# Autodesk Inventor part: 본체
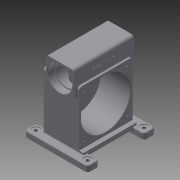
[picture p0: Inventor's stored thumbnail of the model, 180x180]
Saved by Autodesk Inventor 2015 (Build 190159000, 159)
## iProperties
Created: 2025-06
Part Number: 본체
Material: 일반
Document SubType Name: Modeling
Designer: User
Density: 1 g/cm^3
Appearance: 기본값
Author: User
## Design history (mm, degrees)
sketch "스케치1"
  geometry: L1 (-93, -103)-(93, -103); L2 (93, -103)-(93, 103); L3 (93, 103)-(-93, 103); L4 (-93, 103)-(-93, -103); L5 (-93, -103)-(93, 103); L6 (93, -103)-(-93, 103); 1 further point
  constraints: 12 end point, 2 midpoint, 2 parallel, 1 horizontal, 1 perpendicular
  dimensions: "d0" = 186 distance of L3.end L2.end; "d1" = 206 distance of L2.end L1.end
extrude "돌출1" new body sketch "스케치1" distance "d2" = 125; taper "d3" = 0 deg
sketch "스케치2"
  geometry: L1 (103, -93)-(103, 93) reference; L2 (103, 93)-(-103, 93) reference; L3 (103, -93)-(86, -93); L4 (86, -93)-(86, 93); L5 (86, 93)-(103, 93); L6 (103, 93)-(103, -93); 1 further point
  constraints: 8 end point, 2 parallel, 1 horizontal, 1 perpendicular, 1 point on line
  dimensions: "d4" = 17 distance between parallel lines of L1 L4
extrude "돌출2" join sketch "스케치2" distance "d5" = 15; taper "d6" = 0 deg
node "작업 평면1"
sketch "스케치3"
  geometry: L1 (-22, 158)-(-118, 158); L2 (-118, 158)-(-118, 62); L3 (-118, 62)-(-22, 62); L4 (-22, 62)-(-22, 158); L5 (-22, 158)-(-118, 62); L6 (-118, 158)-(-22, 62); L7 (0, -103)-(0, 103) reference; L8 (0, -103)-(-140, -103) reference; 2 further points
  constraints: 12 end point, 2 midpoint, 2 parallel, 1 horizontal, 1 perpendicular
  dimensions: "d8" = 96 distance of L3.end L2.end; "d9" = 96 distance of L2.end L1.end; "d10" = 70 distance from line of L7 point (-70, 110); "d11" = 261 distance between parallel lines of L8 L1
extrude "돌출3" join sketch "스케치3" stored distance "d12" = 210; taper "d13" = 0 deg
fillet "모깎기1" dims "d14" = 10
sketch "스케치4"
  geometry: A1 r 10 centre (108, -72) between (118, -72) and (108, -62) reference; A2 r 10 centre (32, -72) between (32, -62) and (22, -72) reference; A3 r 10 centre (32, -148) between (22, -148) and (32, -158) reference; A4 r 10 centre (108, -148) between (108, -158) and (118, -148) reference; 1 further point
hole "구멍1" sketch "스케치4" at (108, -148), (32, -148), (108, -72), (32, -72) diameter "d15" = 4.917; stored, may be unused: countersink angle "d19" = 90 deg, drill point angle "d21" = 118 deg; dims "d16" = 12, "d17" = 4, "d18" = 2, "d20" = 14
sketch "스케치5"
  geometry: L1 (32, -158)-(108, -158) reference; L2 (118, -148)-(118, -72) reference; 2 further points
  dimensions: "d22" = 48 distance from line of L2 point (70, -110); "d23" = 48 distance from line of L1 point (70, -110)
hole "구멍2" sketch "스케치5" at (70, -110) diameter "d24" = 77; stored, may be unused: countersink angle "d28" = 90 deg, drill point angle "d30" = 118 deg; dims "d25" = 16, "d26" = 85, "d27" = 23, "d29" = 18
sketch "스케치6"
  geometry: L1 (103, -93)-(103, 93) reference; C1 r 86 at (-10, 0); 1 further point
  constraints: 1 centre point, 1 horizontal alignment
  dimensions: "d31" = 172 diameter of C1; "d32" = 113 distance from line of L1 C1.centre
extrude "돌출4" cut sketch "스케치6" distance "d33" = 102; taper "d34" = 0 deg
sketch "스케치7"
  geometry: C1 r 86 at (0, 0) reference; 1 further point
hole "구멍3" sketch "스케치7" at (0, 0) diameter "d35" = 54; stored, may be unused: countersink angle "d39" = 90 deg, drill point angle "d41" = 0 deg; dims "d36" = 16, "d37" = 62, "d38" = 16, "d40" = 19
fillet "모깎기2" dims "d42" = 1
sketch "스케치8"
  geometry: L1 (0, 186)-(-140, 186) reference; L2 (-140, 0)-(-140, 186) reference; L3 (0, 0)-(-140, 0) reference; L4 (-170, -25)-(30, -25); L5 (40, -15)-(40, 5); L6 (30, 15)-(-170, 15); L7 (-180, 5)-(-180, -15); L8 (-70, 0)-(-70, 186); L9 (-140, 93)-(0, 93); L10 (-125, 7)-(-125, 179) reference; A1 r 10 centre (-170, -15) between (-180, -15) and (-170, -25); A2 r 10 centre (-170, 5) between (-170, 15) and (-180, 5); A3 r 10 centre (30, -15) between (30, -25) and (40, -15); A4 r 10 centre (30, 5) between (40, 5) and (30, 15)
  constraints: 12 end point, 8 point on circle, 8 tangent, 4 centre point, 3 equal radius, 3 midpoint, 2 parallel, 2 perpendicular, 1 horizontal
  dimensions: "d43" = 40 distance between parallel lines of L6 L4; "d44" = 10 radius of A1; "d45" = 220 distance between parallel lines of L5 L7; "d46" = 110 distance between parallel lines of L8 L7; "d47" = 118 distance from line of L4 L9.start
extrude "돌출5" join sketch "스케치8" stored distance "d48" = 20; taper "d49" = 0 deg
fillet "모깎기3" dims "d50" = 10
sketch "스케치9"
  geometry: C1 r 86 at (-10, 0) reference; 5 further points
  constraints: 2 horizontal alignment, 2 vertical alignment
  dimensions: "d51" = 75 vertical distance of point (0, 0) point (-85, -75); "d53" = 150 distance of point (-85, 75) point (-85, -75); "d54" = 150 distance of point (65, -75) point (-85, -75); "d84" = 75 horizontal distance of C1.centre point (-85, -75)
hole "구멍4" sketch "스케치9" at (-85, -75), (-85, 75), (65, 75), (65, -75) diameter "d55" = 6.647; stored, may be unused: countersink angle "d59" = 90 deg, drill point angle "d61" = 118 deg; dims "d56" = 16, "d57" = 62, "d58" = 16, "d60" = 18
sketch "스케치10"
  geometry: L1 (0, 0)-(140, 0) reference; L2 (-30, -25)-(170, -25) reference; L3 (70, 0)-(70, -25); C1 r 14 at (-20, -5); C2 r 14 at (160, -5); 1 further point
  constraints: 2 centre point, 2 end point, 2 midpoint, 1 horizontal alignment
  dimensions: "d62" = 28 diameter of C1; "d63" = 28 diameter of C2; "d64" = 180 distance of C2.centre C1.centre; "d66" = 20 distance from line of L2 C1.centre; "d67" = 90 distance from line of L3 C1.centre
hole "구멍5" sketch "스케치10" at (-20, -5), (160, -5) diameter "d68" = 11; stored, may be unused: countersink angle "d72" = 90 deg, drill point angle "d74" = 0 deg; dims "d69" = 16, "d70" = 28, "d71" = 2, "d73" = 18
fillet "모깎기4" dims "d75" = 1.1
chamfer "모따기1" distance "d76" = 1; stored, may be unused: second distance "d77" = 2, angle "d78" = 45 deg
fillet "모깎기5" dims "d79" = 3
fillet "모깎기6" dims "d80" = 3
sketch "스케치11"
  geometry: L1 (-10, 210)-(-10, 0) reference; 2 further points
  constraints: 1 horizontal alignment, 1 other
  dimensions: "d81" = 30 distance from line of L1 point (20, 105)
feature "엠보싱1" sketch "스케치11" dims "d0" = 186, "d1" = 206, "d8" = 96, "d9" = 96, "d10" = 70, "d11" = 261, "d82" = 0.5, "d83" = 0
node "솔리드1"
mirror "대칭1"
mirror "대칭2"
mirror "대칭3"
mirror "대칭4"
other parameters: "d7" = 0
